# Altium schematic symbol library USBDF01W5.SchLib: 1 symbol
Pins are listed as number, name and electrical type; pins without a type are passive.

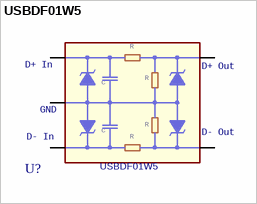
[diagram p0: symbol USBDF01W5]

## USBDF01W5
designator U?
footprint ST_SOT323-5L
pins: 1 D+ In, 2 GND, 3 D- In, 4 D- Out, 5 D+ Out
